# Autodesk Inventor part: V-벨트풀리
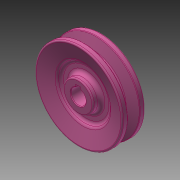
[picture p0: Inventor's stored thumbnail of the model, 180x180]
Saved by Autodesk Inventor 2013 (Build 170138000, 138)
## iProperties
Created: 2016-08
Part Number: V-벨트풀리
Material: 알루미늄 6061
Document SubType Name: Modeling
Designer: mduedu
Density: 2.71 g/cm^3
Author: mduedu
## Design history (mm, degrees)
sketch "스케치1"
  geometry: L1 (0, 9.5)-(0, -9.5); L2 (0, 9.5)-(35, 9.5); L3 (35, 9.5)-(35, 4.825); L4 (35, 4.825)-(26, 2.074); L5 (26, 2.074)-(26, 0); L6 (0, 0)-(26, 0); L7 (0, -9.5)-(35, -9.5); L8 (35, -9.5)-(35, -4.825); L9 (35, -4.825)-(26, -2.074); L10 (26, -2.074)-(26, 0); L11 (32.3, 9.5)-(32.3, -9.5); 3 further points
  constraints: 22 end point, 6 point on line, 4 perpendicular, 3 symmetric about line, 1 coincident, 1 horizontal alignment, 1 midpoint, 1 parallel, 1 vertical
  dimensions: "d0" = 19 distance of L1.start L1.end; "d2" = 70 diameter of L8 L1; "d4" = 6.3 distance between parallel lines of L10 L11; "d5" = 2.7 distance between parallel lines of L11 L8; "d6" = 8 distance of point (32.3, -4) point (32.3, 4); "d7" = 34 deg angle of L9 L4
revolve "회전1" sketch "스케치1" stored, may be unused: angle "d8" = 90 deg
sketch "스케치2"
  geometry: L1 (-2, 0)-(2, 0); L2 (2, 0)-(2, 7.8); L3 (2, 7.8)-(-2, 7.8); L4 (-2, 7.8)-(-2, 0); C1 r 6 at (0, 0); 2 further points
  constraints: 8 end point, 2 coincident, 2 parallel, 1 centre point, 1 horizontal, 1 midpoint, 1 perpendicular
  dimensions: "d9" = 12 diameter of C1; "d11" = 4 distance of L2.end L3.end; "d12" = 7.8 distance of L1.end L2.end
extrude "돌출1" cut sketch "스케치2" stored distance "d13" = 10; taper "d14" = 0 deg
sketch "스케치3"
  geometry: L1 (35, 4.825)-(26, 2.074) reference; L2 (26, 2.074)-(26, -2.074) reference; L3 (0, 0)-(26, 0); L4 (35, 9.5)-(35, 4.825) reference; L5 (-35, 9.5)-(35, 9.5) reference; L6 (35, 9.5)-(21, 5.22); L7 (21, 5.22)-(21, 3); L8 (21, 3)-(12, 3); L9 (12, 3)-(12, 9.5); L10 (0, 9.5)-(0, -9.5); L11 (5.657, -9.5)-(-6, -9.5) reference; L12 (12, 9.5)-(35, 9.5)
  constraints: 14 end point, 3 midpoint, 2 parallel, 2 perpendicular, 2 point on line, 1 collinear, 1 horizontal
  dimensions: "d15" = 3 distance between parallel lines of L3 L8; "d17" = 42 diameter of L7 L10; "d18" = 24 diameter of L9 L10
revolve "회전2" sketch "스케치3" stored, may be unused: angle "d19" = 90 deg
fillet "모깎기1" dims "d20" = 0.5, "d21" = 1, "d22" = 1
fillet "모깎기2" dims "d23" = 3
fillet "모깎기3" dims "d24" = 3
fillet "모깎기4" dims "d25" = 3
chamfer "모따기1" distance "d26" = 0.5; stored, may be unused: second distance "d27" = 2, angle "d28" = 45 deg
fillet "모깎기5" dims "d29" = 1
node "솔리드1"
mirror "대칭1"
